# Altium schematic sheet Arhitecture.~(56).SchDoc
size A3; SheetNumber: 1; SheetTotal: 14
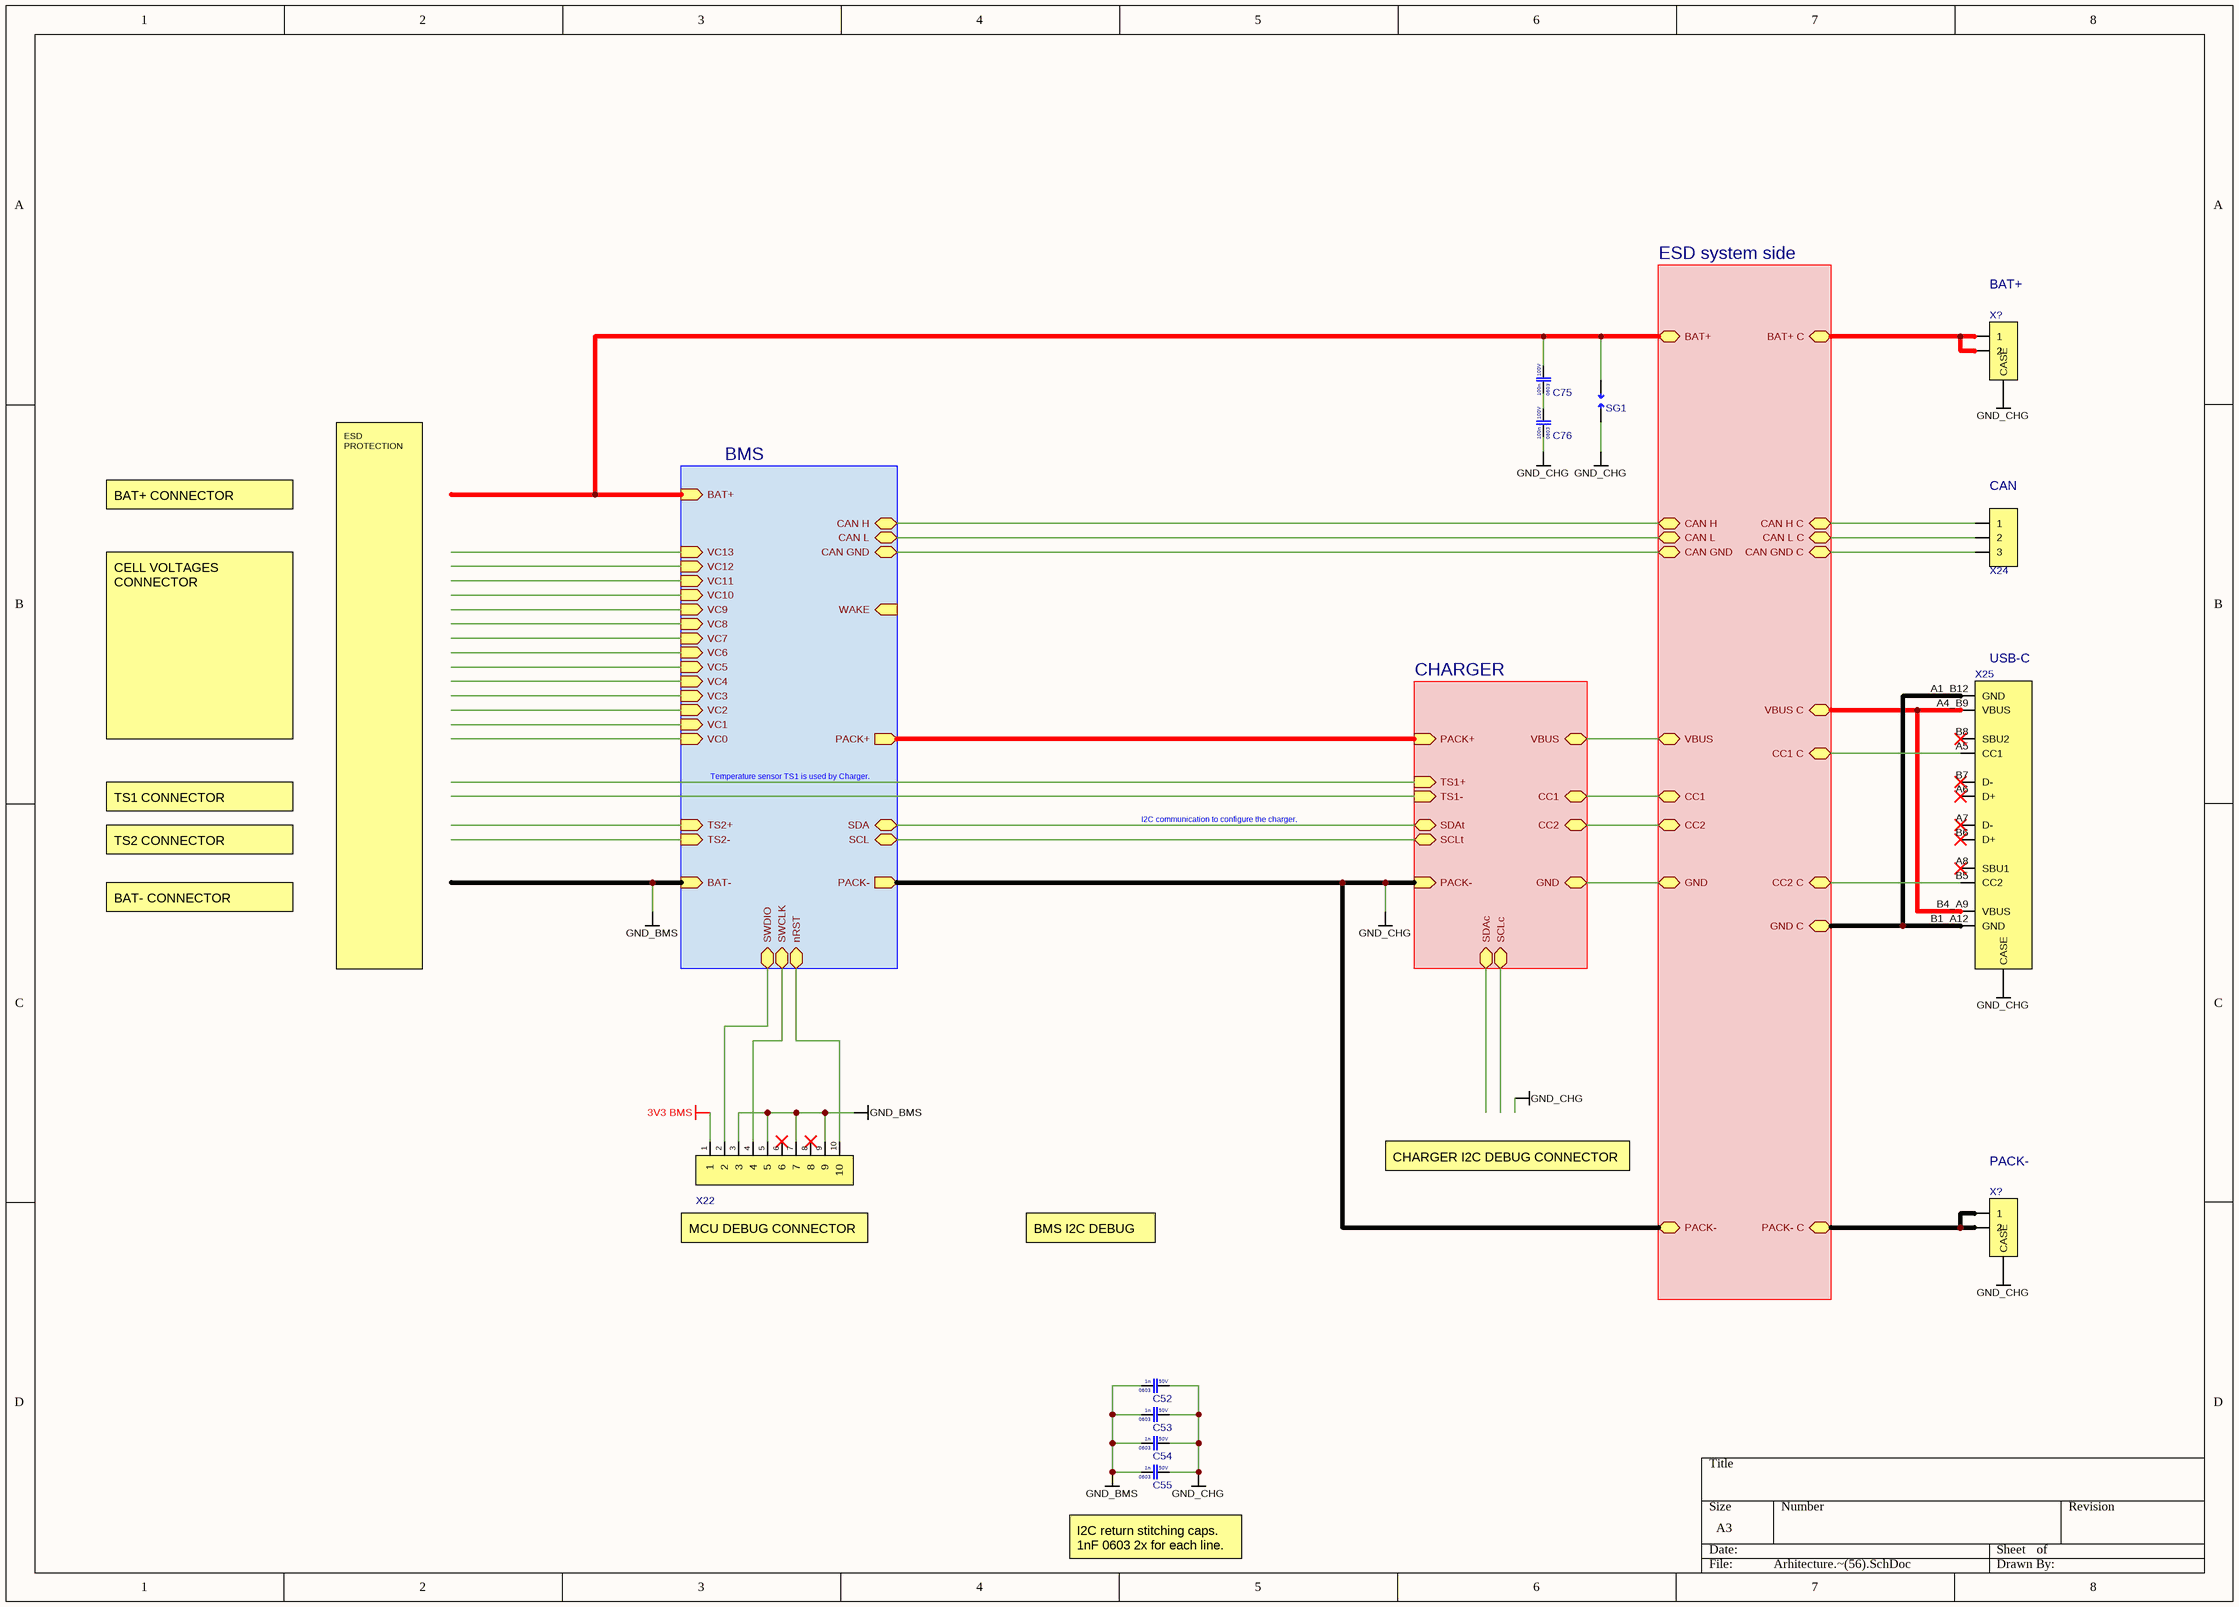
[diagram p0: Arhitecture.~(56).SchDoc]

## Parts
(Parts that share a designator on the sheet are numbered #1, #2 ... from top to bottom, then left to right.)
C52  Voltage Rating: 50V  Case Code (Imperial): 0603  Capacitance: 1n  [CAP 0603]  (hidden comment: CL10B102KB8NNNC)
C53  Voltage Rating: 50V  Case Code (Imperial): 0603  Capacitance: 1n  [CAP 0603]  (hidden comment: CL10B102KB8NNNC)
C54  Voltage Rating: 50V  Case Code (Imperial): 0603  Capacitance: 1n  [CAP 0603]  (hidden comment: CL10B102KB8NNNC)
C55  Voltage Rating: 50V  Case Code (Imperial): 0603  Capacitance: 1n  [CAP 0603]  (hidden comment: CL10B102KB8NNNC)
C75  Voltage Rating: 100V  Case Code (Imperial): 0603  Capacitance: 100n  [CAP 0603]  (hidden comment: CC0603KRX7R0BB104)
C76  Voltage Rating: 100V  Case Code (Imperial): 0603  Capacitance: 100n  [CAP 0603]  (hidden comment: CC0603KRX7R0BB104)
SG1  Spark gap  [Spark Gap 0.270mm]  (value not drawn)  (no BOM)
X22  HX IDC127-2-05-S-4.9  [JTAG Cortex connector]  (value not drawn)
X24  S3B-XH-A-1(LF)(SN)  [S3B-XH-A-1(LF)(SN)]  (value not drawn)
X25  USB-TYPE-C-018  [TYPE-C 16PIN 2MD]  (value not drawn)
X?#1  XT30PW-M30.G.Y  [XT30PW-M30.G.Y]  (value not drawn)
X?#2  XT30PW-M30.G.Y  [XT30PW-M30.G.Y]  (value not drawn)

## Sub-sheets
BMS = BMS.SchDoc: BAT+ (in), BAT- (in), VC0 (in), VC1 (in), VC2 (in), VC3 (in), VC4 (in), VC5 (in), VC6 (in), VC7 (in), VC8 (in), VC9 (in), VC10 (in), VC11 (in), VC12 (in), VC13 (in), PACK+ (out), PACK- (out), SCL (bidir), SDA (bidir), CAN H (bidir), CAN L (bidir), TS2+ (in), TS2- (in), WAKE (in), SWDIO (bidir), SWCLK (bidir), nRST (bidir), CAN GND (bidir)
CHARGER = CHARGER.SchDoc: PACK+ (in), PACK- (in), SDAt (bidir), SCLt (bidir), TS1+ (in), TS1- (in), SDAc (bidir), SCLc (bidir), CC1 (bidir), CC2 (bidir), GND (bidir), VBUS (bidir)
ESD system side = ESD system side.SchDoc: CAN H (bidir), CAN L (bidir), CAN GND (bidir), CAN H C (bidir), CAN L C (bidir), CAN GND C (bidir), VBUS C (bidir), GND C (bidir), CC1 C (bidir), CC2 C (bidir), VBUS (bidir), CC1 (bidir), CC2 (bidir), GND (bidir), BAT+ C (bidir), BAT+ (bidir), PACK- C (bidir), PACK- (bidir)

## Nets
3V3 BMS: X22.1
GND_BMS: C52.1 C53.1 C54.1 C55.1 X22.3 X22.5 X22.7 X22.9 ; sheet BMS/BAT-
GND_CHG: C52.2 C53.2 C54.2 C55.2 C76.1 SG1.1 X25.CASE X?#1.CASE X?#2.CASE ; sheet BMS/PACK-, sheet CHARGER/PACK-, sheet ESD system side/PACK-
NetC75_1: C75.1 C76.2
NetC75_2: C75.2 SG1.2 ; sheet BMS/BAT+, sheet ESD system side/BAT+
NetX22_2: X22.2 ; sheet BMS/SWDIO
NetX22_4: X22.4 ; sheet BMS/SWCLK
NetX22_10: X22.10 ; sheet BMS/nRST
NetX24_1: X24.1 ; sheet ESD system side/CAN H C
NetX24_2: X24.2 ; sheet ESD system side/CAN L C
NetX24_3: X24.3 ; sheet ESD system side/CAN GND C
NetX25_A1_B12: X25.A1_B12(GND) X25.B1_A12(GND) ; sheet ESD system side/GND C
NetX25_A4_B9: X25.A4_B9(VBUS) X25.B4_A9(VBUS) ; sheet ESD system side/VBUS C
NetX25_A5: X25.A5(CC1) ; sheet ESD system side/CC1 C
NetX25_B5: X25.B5(CC2) ; sheet ESD system side/CC2 C
NetX?#1_1: X?#1.1 X?#1.2 ; sheet ESD system side/BAT+ C
NetX?#2_1: X?#2.1 X?#2.2 ; sheet ESD system side/PACK- C
(unnamed): sheet BMS/PACK+, sheet CHARGER/PACK+
(unnamed): sheet BMS/SCL, sheet CHARGER/SCLt  [a separate net that carries the same name]
(unnamed): sheet BMS/SDA, sheet CHARGER/SDAt  [a separate net that carries the same name]
(unnamed): sheet BMS/CAN H, sheet ESD system side/CAN H  [a separate net that carries the same name]
(unnamed): sheet BMS/CAN L, sheet ESD system side/CAN L  [a separate net that carries the same name]
(unnamed): sheet BMS/CAN GND, sheet ESD system side/CAN GND  [a separate net that carries the same name]
(unnamed): sheet CHARGER/CC1, sheet ESD system side/CC1  [a separate net that carries the same name]
(unnamed): sheet CHARGER/CC2, sheet ESD system side/CC2  [a separate net that carries the same name]
(unnamed): sheet CHARGER/GND, sheet ESD system side/GND  [a separate net that carries the same name]
(unnamed): sheet CHARGER/VBUS, sheet ESD system side/VBUS  [a separate net that carries the same name]

Not connected (* = marked no-connect by the designer): X22 6* 8*; X25 A6(D+)* A7(D-)* A8(SBU1)* B6(D+)* B7(D-)* B8(SBU2)*

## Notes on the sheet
- (near X?#1) BAT+
- BAT+ CONNECTOR
- (near X24) CAN
- (near X25) USB-C
- CELL VOLTAGES CONNECTOR
- TS1 CONNECTOR
- Temperature sensor TS1 is used by Charger.
- I2C communication to configure the charger.
- BAT- CONNECTOR
- TS2 CONNECTOR
- ESD PROTECTION
- CHARGER I2C DEBUG CONNECTOR
- (near X?#2) PACK-
- MCU DEBUG CONNECTOR
- BMS I2C DEBUG CONNECTOR
- (near C55) I2C return stitching caps.
  1nF 0603 2x for each line.

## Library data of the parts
C52-C55 = CL10B102KB8NNNC: Cap 1nF 50V 0603 X7R; Manufacturer: Samsung
C75 C76 = CC0603KRX7R0BB104: Cap 100nF 100V 0603 X7R; Manufacturer: YAGEO
SG1 = Spark gap: Generic Spark gap symbol
X22 = HX IDC127-2-05-S-4.9: JTAG Cortex MCU Debug connector 2x5P 1.27mmP; Manufacturer: hanxia
X24 = S3B-XH-A-1(LF)(SN): JST XH 1x3 2.50mmP THT Right-angle
X25 = USB-TYPE-C-018: USB-C 16P Right-angle; Manufacturer: DEALON
X?#1 X?#2 = XT30PW-M30.G.Y: XT30 Male THT Right-angle; Manufacturer: Changzhou Amass Elec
